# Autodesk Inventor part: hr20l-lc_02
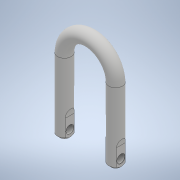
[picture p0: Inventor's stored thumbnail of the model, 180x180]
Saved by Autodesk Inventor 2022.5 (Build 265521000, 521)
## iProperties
Part Number: hr20l-lc_02
Material: 一般
Document SubType Name: Modeling
Designer: ImaoCorp
Density: 1 g/cm^3
Appearance: 既定
Author: ImaoCorp
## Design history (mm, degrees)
feature "hr20l-lc_02"
node "ソリッド1"
